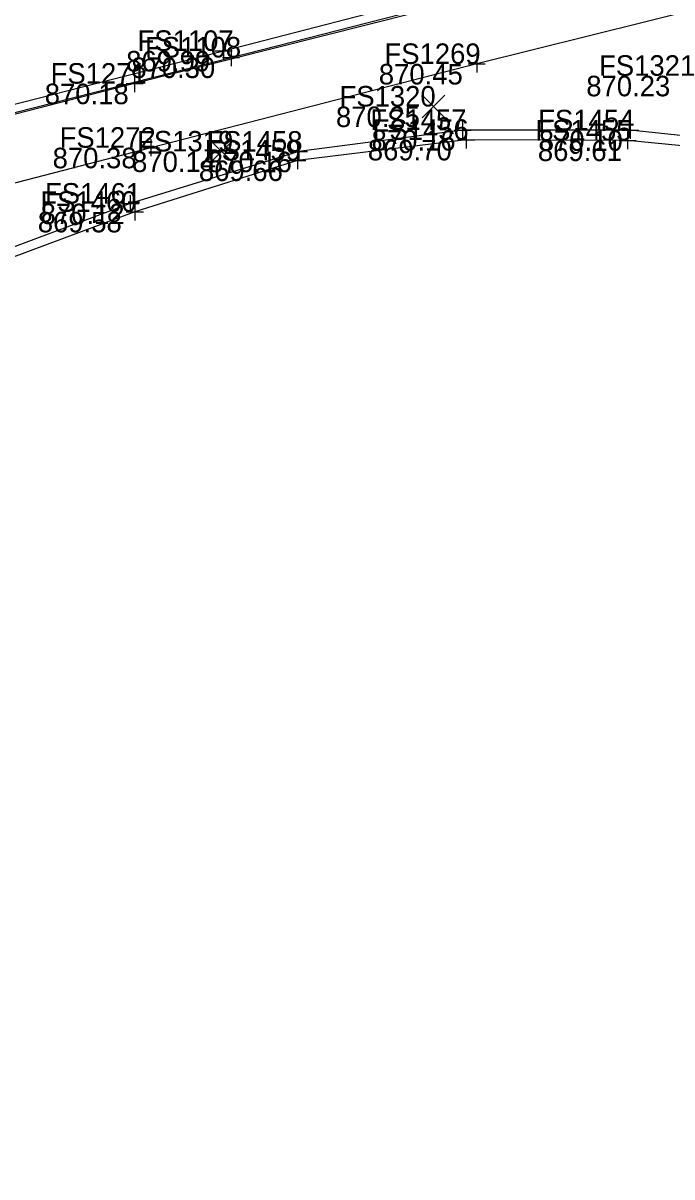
# Model space of a CAD drawing. Extents: x 1479420 to 1479833, y 379731 to 380103.
# Drawn here: x 1479555 to 1479593, y 379796.9 to 379864.3 of the extents above; entities that cross this region are included whole.
import ezdxf

# ---------------------------------------------------------------- set-up
doc = ezdxf.new("R2010")
doc.units = 0
for name, color, linetype in [('PV_X_Curb', 7, 'Continuous'), ('PV_X_Walk', 7, 'Continuous'), ('SV_X_Random_Point', 7, 'Continuous'), ('SV_X_Shot_Marker', 7, 'Continuous'), ('SV_X_Text_Elevation', 7, 'Continuous'), ('SV_X_Text_Name', 7, 'Continuous')]:
    doc.layers.add(name, color=color, linetype=linetype)

msp = doc.modelspace()

# ---------------------------------------------------------------- linework, layer by layer
at = {"layer": 'PV_X_Curb'}
for points in [[(1479448.263, 379811.446), (1479461.223, 379819.505), (1479478.3, 379830.094), (1479484.788, 379833.845), (1479492.119, 379838.16), (1479500.701, 379842.975), (1479508.918, 379847.117), (1479516.087, 379849.63), (1479529.031, 379853.073), (1479547.645, 379857.816), (1479566.743, 379862.68), (1479585.84, 379867.633), (1479595.941, 379870.21)], [(1479448.497, 379810.926), (1479461.699, 379819.081), (1479478.683, 379829.765), (1479485.034, 379833.446), (1479492.452, 379837.857), (1479500.924, 379842.633), (1479509.095, 379846.687), (1479516.116, 379849.207), (1479529.309, 379852.683), (1479547.62, 379857.329), (1479567.188, 379862.296), (1479585.958, 379867.104), (1479596.074, 379869.8)], [(1479601.319, 379856.891), (1479590.521, 379858.038), (1479580.718, 379858.057), (1479571.147, 379856.791), (1479561.287, 379853.753), (1479553.092, 379850.702), (1479544.73, 379845.631), (1479537.421, 379839.852), (1479530.35, 379833.145), (1479518.148, 379820.183), (1479506.748, 379808.804), (1479505.037, 379808.132), (1479502.743, 379808.986), (1479490.356, 379819.723), (1479452.909, 379780.6)], [(1479601.347, 379856.369), (1479590.364, 379857.442), (1479580.925, 379857.48), (1479571.059, 379856.275), (1479561.558, 379853.273), (1479553.285, 379850.192), (1479545.205, 379845.234), (1479537.871, 379839.395), (1479530.786, 379832.841), (1479518.522, 379819.829), (1479508.592, 379809.053), (1479504.774, 379807.6), (1479502.376, 379808.454), (1479490.367, 379818.943), (1479453.507, 379780.799)]]:
    msp.add_lwpolyline(points, dxfattribs=at)
at = {"layer": 'PV_X_Walk'}
for points in [[(1479600.533, 379870.638), (1479580.734, 379865.6), (1479561.549, 379860.766), (1479542.709, 379855.919), (1479519.925, 379850.15), (1479513.475, 379848.178), (1479509.191, 379846.567), (1479504.249, 379844.075), (1479496.362, 379839.934), (1479478.251, 379829.275), (1479450.128, 379811.818)], [(1479601.313, 379866.859), (1479581.547, 379861.918), (1479562.5, 379857.02), (1479543.703, 379852.153), (1479520.939, 379846.407), (1479515.035, 379844.633), (1479510.748, 379842.941), (1479506.291, 379840.861), (1479498.375, 379836.477), (1479480.408, 379825.918), (1479452.204, 379808.527)]]:
    msp.add_lwpolyline(points, dxfattribs=at)
at = {"layer": 'SV_X_Random_Point'}
for p, q in [((1479578.346, 379858.761), (1479579.68, 379860.096)), ((1479578.346, 379860.096), (1479579.68, 379858.761)), ((1479565.967, 379856.135), (1479567.301, 379857.47)), ((1479565.967, 379857.47), (1479567.301, 379856.135))]:
    msp.add_line(p, q, dxfattribs=at)
at = {"layer": 'SV_X_Shot_Marker'}
for p, q in [((1479566.743, 379863.18), (1479566.743, 379862.18)), ((1479566.243, 379862.68), (1479567.243, 379862.68)), ((1479566.743, 379862.68), (1479566.743, 379862.68)), ((1479567.188, 379862.796), (1479567.188, 379861.796)), ((1479581.547, 379862.418), (1479581.547, 379861.418)), ((1479566.688, 379862.296), (1479567.688, 379862.296)), ((1479567.188, 379862.296), (1479567.188, 379862.296)), ((1479581.047, 379861.918), (1479582.047, 379861.918)), ((1479581.547, 379861.918), (1479581.547, 379861.918)), ((1479561.549, 379861.266), (1479561.549, 379860.266)), ((1479561.049, 379860.766), (1479562.049, 379860.766)), ((1479561.549, 379860.766), (1479561.549, 379860.766)), ((1479580.718, 379858.557), (1479580.718, 379857.557)), ((1479590.521, 379858.538), (1479590.521, 379857.538)), ((1479580.218, 379858.057), (1479581.218, 379858.057)), ((1479580.718, 379858.057), (1479580.718, 379858.057)), ((1479580.925, 379857.98), (1479580.925, 379856.98)), ((1479590.021, 379858.038), (1479591.021, 379858.038)), ((1479590.364, 379857.942), (1479590.364, 379856.942)), ((1479590.521, 379858.038), (1479590.521, 379858.038)), ((1479562, 379857.02), (1479563, 379857.02)), ((1479562.5, 379857.52), (1479562.5, 379856.52)), ((1479562.5, 379857.02), (1479562.5, 379857.02)), ((1479571.147, 379857.291), (1479571.147, 379856.291)), ((1479580.425, 379857.48), (1479581.425, 379857.48)), ((1479580.925, 379857.48), (1479580.925, 379857.48)), ((1479589.864, 379857.442), (1479590.864, 379857.442)), ((1479590.364, 379857.442), (1479590.364, 379857.442)), ((1479570.647, 379856.791), (1479571.647, 379856.791)), ((1479571.059, 379856.775), (1479571.059, 379855.775)), ((1479571.147, 379856.791), (1479571.147, 379856.791)), ((1479570.559, 379856.275), (1479571.559, 379856.275)), ((1479571.059, 379856.275), (1479571.059, 379856.275)), ((1479560.787, 379853.753), (1479561.787, 379853.753)), ((1479561.287, 379854.253), (1479561.287, 379853.253)), ((1479561.287, 379853.753), (1479561.287, 379853.753)), ((1479561.558, 379853.773), (1479561.558, 379852.773)), ((1479561.058, 379853.273), (1479562.058, 379853.273)), ((1479561.558, 379853.273), (1479561.558, 379853.273))]:
    msp.add_line(p, q, dxfattribs=at)

# ---------------------------------------------------------------- texts
at = {"layer": 'SV_X_Text_Elevation'}
for s, p in [('869.99', (1479561.055, 379861.48)), ('870.30', (1479561.349, 379861.096)), ('870.45', (1479575.822, 379860.718)), ('870.23', (1479587.949, 379860.027)), ('870.18', (1479556.296, 379859.566)), ('870.25', (1479573.316, 379858.229)), ('870.16', (1479575.399, 379856.857)), ('870.10', (1479585.174, 379856.838)), ('870.38', (1479556.755, 379855.82)), ('869.70', (1479575.18, 379856.28)), ('869.61', (1479585.119, 379856.242)), ('870.14', (1479561.4, 379855.602)), ('869.66', (1479565.305, 379855.075)), ('870.16', (1479565.828, 379855.591)), ('870.12', (1479556.053, 379852.553)), ('869.58', (1479555.889, 379852.073))]:
    msp.add_text(s, height=1.2, dxfattribs=at).set_placement(p)
at = {"layer": 'SV_X_Text_Name'}
for s, p in [('FS1107', (1479561.718, 379862.68)), ('FS1108', (1479562.153, 379862.296)), ('FS1269', (1479576.153, 379861.918)), ('FS1321', (1479588.695, 379861.227)), ('FS1271', (1479556.636, 379860.766)), ('FS1320', (1479573.524, 379859.429)), ('FS1457', (1479575.324, 379858.057)), ('FS1454', (1479585.136, 379858.038)), ('FS1456', (1479575.455, 379857.48)), ('FS1455', (1479584.97, 379857.442)), ('FS1272', (1479557.162, 379857.02)), ('FS1319', (1479561.694, 379856.802)), ('FS1458', (1479565.743, 379856.791)), ('FS1459', (1479565.655, 379856.275)), ('FS1461', (1479556.308, 379853.753)), ('FS1460', (1479556.041, 379853.273))]:
    msp.add_text(s, height=1.2, dxfattribs=at).set_placement(p)

doc.saveas('drawing.dxf')
